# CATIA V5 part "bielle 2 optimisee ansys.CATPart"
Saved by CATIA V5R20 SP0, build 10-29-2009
Part number: Pièce1
Bounding box of the stored display mesh (mm): x -63.008 to 62.454, y -11.642 to 67.669, z 0 to 10
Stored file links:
  C:\Users\Cédric\Documents\IFMA-2A\IAO\Projet IAO\ccascaro\bielle 2 optimisee ansys.CATPart
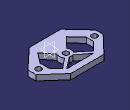
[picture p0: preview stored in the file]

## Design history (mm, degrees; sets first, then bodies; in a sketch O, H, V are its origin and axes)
Body1 (main body)
  Sketch1 on xy-plane, origin (0, 0, 0), H (1, 0, 0), V (0, 1, 0)
    line L1 (-32.1197, 67.6686) -> (28.7287, 67.6686)
    line L2 (28.7287, 67.6686) -> (62.4538, 37.3303)
    line L3 (62.4538, 37.3303) -> (62.4538, 22.9724)
    line L4 (62.4538, 22.9724) -> (25.6775, -11.6416)
    line L5 (25.6775, -11.6416) -> (-32.1197, -11.6416)
    line L6 (-32.1197, -11.6416) -> (-63.008, 21.1764)
    line L7 (-63.008, 21.1764) -> (-63.008, 35.5343)
    line L8 (-63.008, 35.5343) -> (-32.1197, 67.6686)
    point P9 (0.2962, 29.9049)
    circle A1 centre (51.0143, 30.7267) radius 5
    circle A2 centre (-52.6559, 29.8853) radius 5
    line L9 (-24.1399, 56.6014) -> (24.8489, 56.6014)
    line L10 (40.5699, 39.8984) -> (40.5699, 23.0253)
    line L11 (40.5699, 23.0253) -> (26.3858, 4.9236)
    line L12 (-25.3828, 5.2006) -> (-43.0167, 23.936)
    line L13 (-43.0167, 23.936) -> (-43.0167, 37.5307)
    line L14 (-43.0167, 37.5307) -> (-28.1039, 53.045)
    line L15 (-28.1039, 53.045) -> (-7.3683, 36.1499)
    line L16 (-24.1399, 56.6014) -> (-2.8412, 39.9123)
    point P22 (-2.8412, 39.9123)
    line L17 (40.5699, 39.8984) -> (28.7287, 52.4793)
    line L18 (28.7287, 52.4793) -> (9.5202, 37.2285)
    line L19 (24.8489, 56.6014) -> (4.1739, 40.1862)
    point P26 (-7.2775, 23.8917)
    line L20 (-7.2775, 23.8917) -> (-25.3828, 5.2006)
    line L21 (10.4934, 24.3013) -> (26.3858, 4.9236)
    arc A3 centre (1.498, 30.0861) radius 10.7416 from (-7.3683, 36.1499) to (-7.2775, 23.8917) ccw
    point P29 (-9.2299, 29.5442)
    arc A4 centre (1.5312, 30.1268) radius 10.6891 from (10.4934, 24.3013) to (9.5202, 37.2285) ccw
    point P31 (12.0528, 28.2416)
    arc A5 centre (1.0125, 31.1856) radius 9.5397 from (-2.8412, 39.9123) to (4.1739, 40.1862) cw
    point P33 (0, 40.6714)
    circle A6 centre (1.0125, 31.1856) radius 5.0833
    horizontal: L1 H, L5 H
    vertical: L3 V, L7 V, L10 V, L13 V
    perpendicularity: L6 L4, L16 L11
    parallelism: L12 L6, L14 L8, L17 L12, L19 L18, L1 L5, L9 L1
    coincidence: L15 P9, L18 P9, P26 L18, A3 P29, P29 L19, A3 P22, A4 P31, P31 L16, A5 P33, P33 V
    tangency: A4 A3, A5 A3, A6 L19
  Pad1: profile Sketch1, direction (0, 0, 1), length 10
